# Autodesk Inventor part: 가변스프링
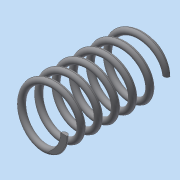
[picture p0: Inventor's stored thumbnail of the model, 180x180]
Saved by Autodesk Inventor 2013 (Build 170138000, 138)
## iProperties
Created: 2018-07
Part Number: 가변스프링
Material: 일반
Document SubType Name: Modeling
Designer: dgall
Density: 1 g/cm^3
Mass: 0.935104 g
Surface Area: 18.9376 cm^2
Volume: 0.935104 cm^3
Author: dgall
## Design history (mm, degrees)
sketch "스케치1"
  geometry: L1 (0, 0)-(0, 32.5); L2 (0, 0)-(8, 0); L3 (0, 32.5)-(8, 32.5); C1 r 1 at (8, 0)
  constraints: 6 end point, 1 centre point, 1 coincident, 1 parallel, 1 perpendicular, 1 vertical
  dimensions: "d0" = 32.5 distance of L1.start L1.end (derived); "d1" = 16 diameter of L2.end L1; "d2" = 16 diameter of L3.end L1; "d3" = 2 diameter of C1
feature "코일1" pitch "d4" = 10; turns "d6" = 6; dims "d5" = 32.5 (= d0), "d7" = 0, angle "d8" = 90 deg, angle "d9" = 90 deg, "d10" = 0, "d11" = 0
node "작업 평면1"
feature "분할1"
node "작업 평면2"
feature "분할2"
node "솔리드1"
other parameters: "d12" = 0, "d13" = 0
